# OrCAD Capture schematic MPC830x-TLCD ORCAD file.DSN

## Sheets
1 1.0_TOP_COVER: title: COVER PAGE; rev: B; company: MICETEK; note: MPC830X-TLCD
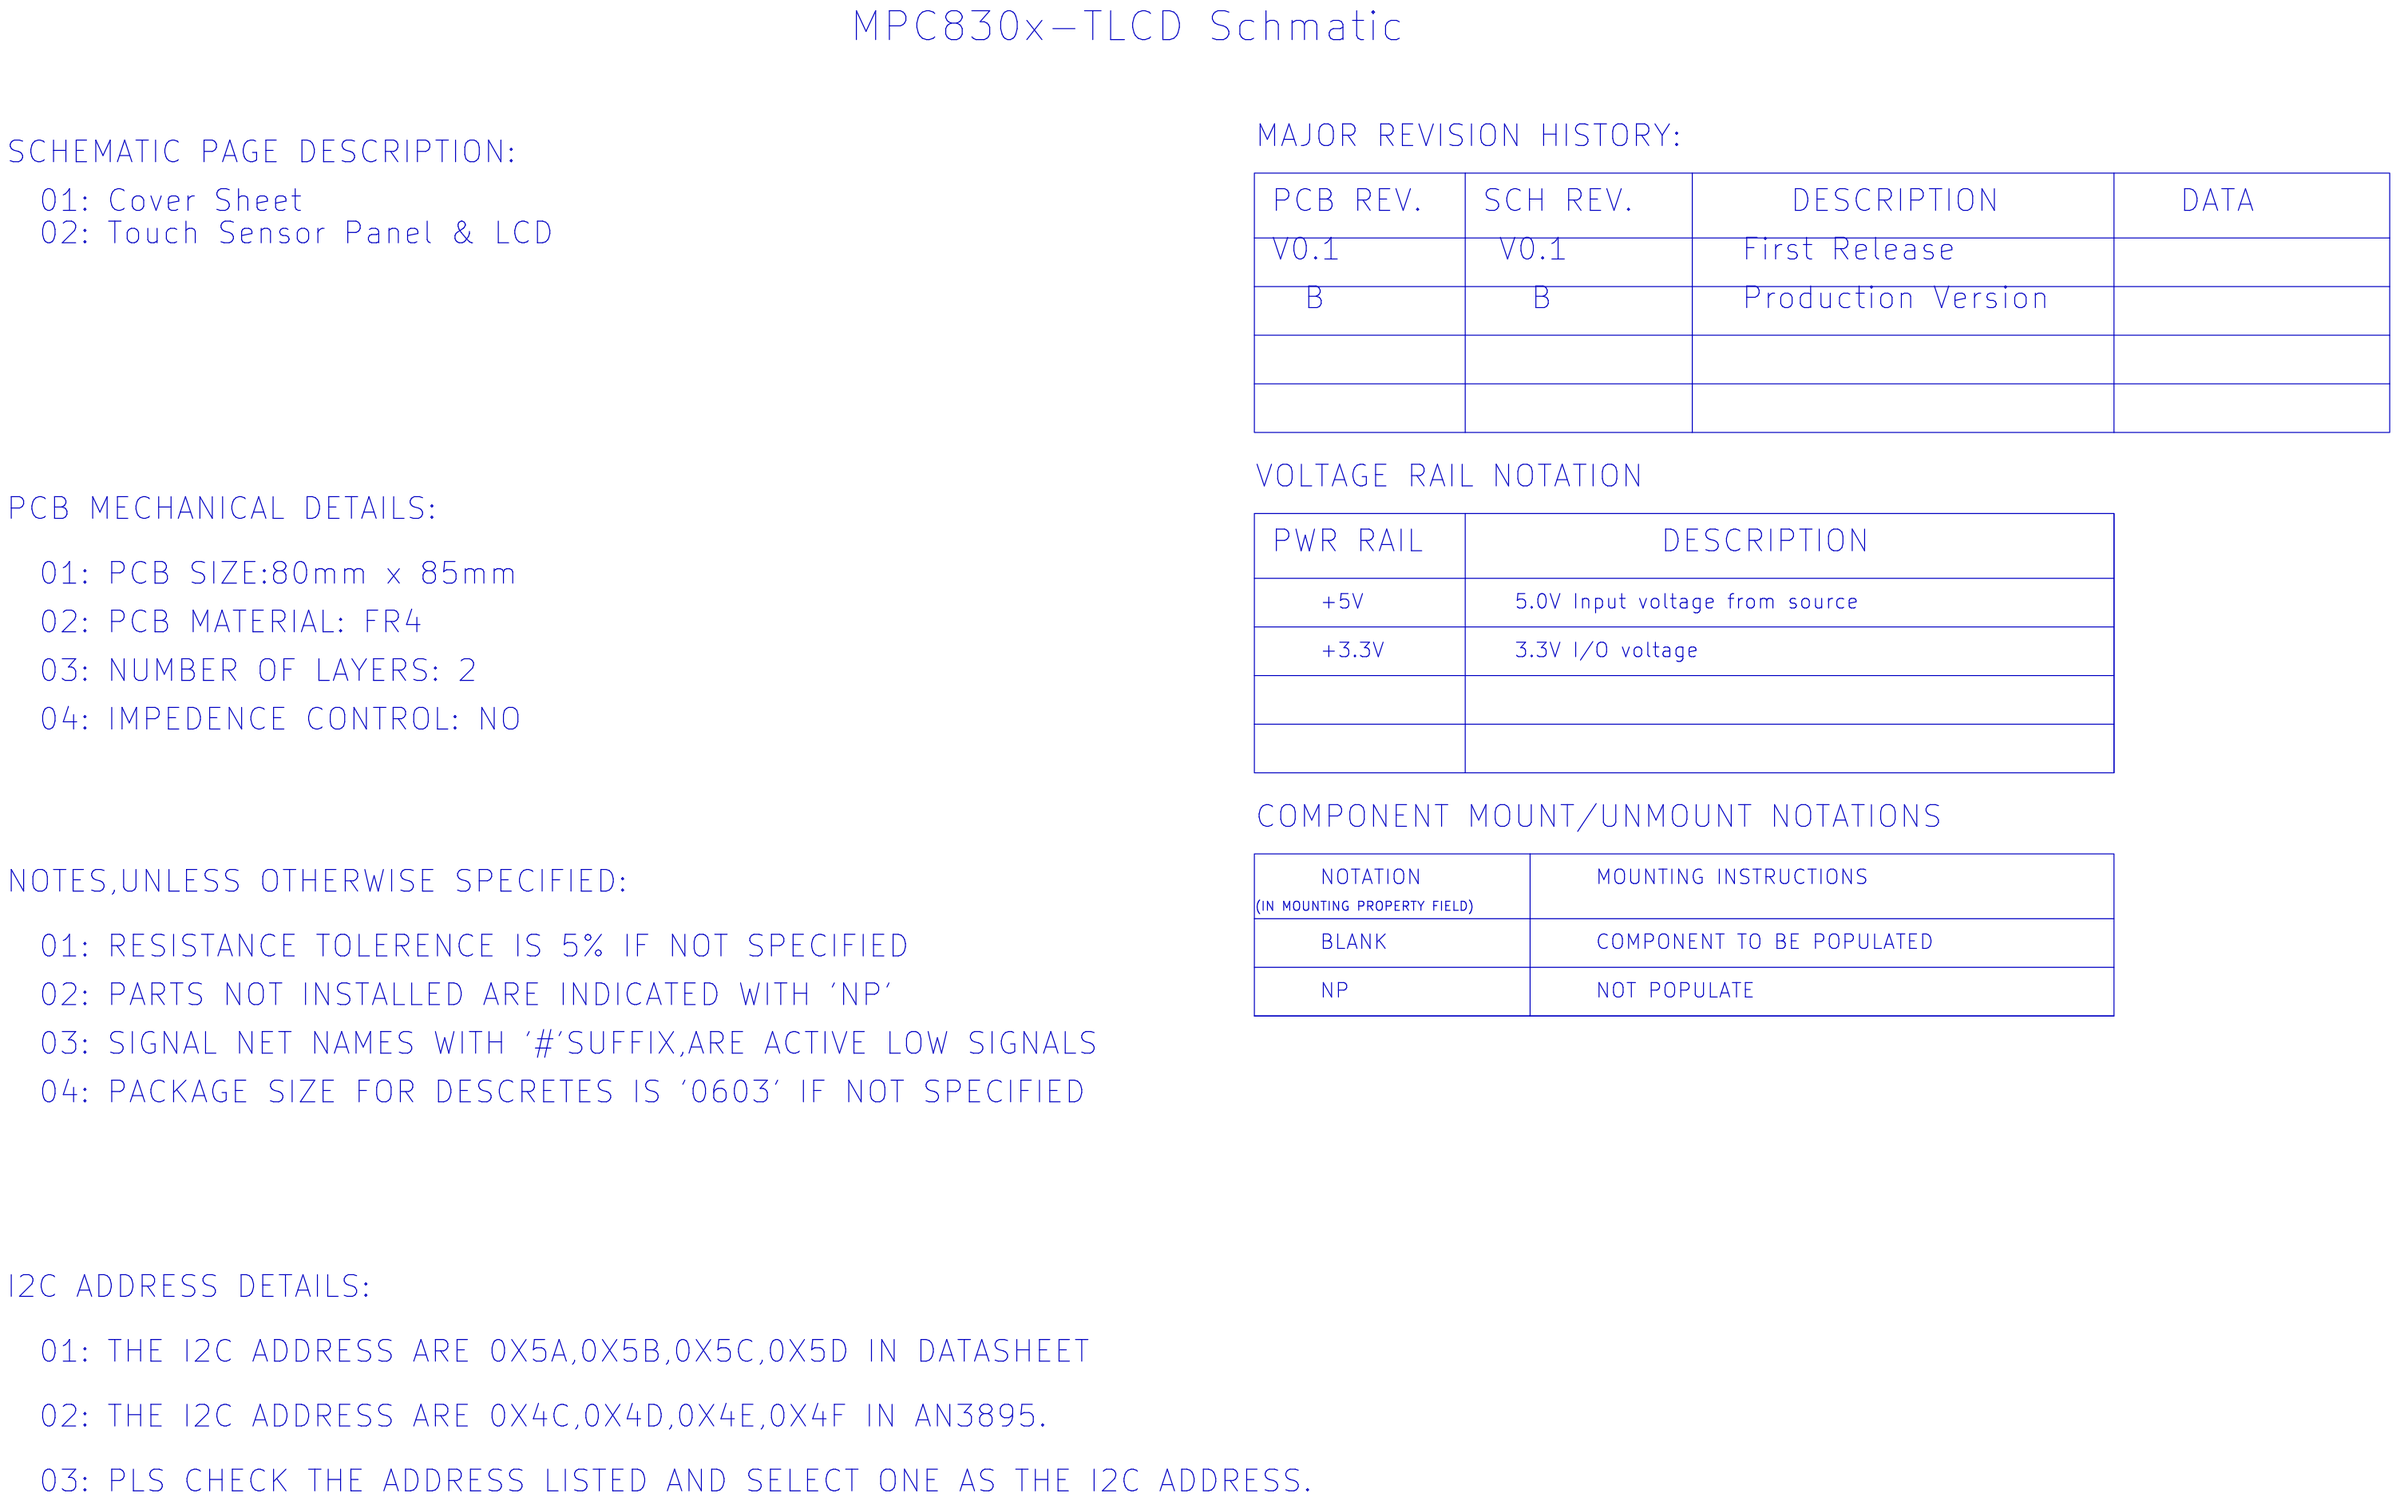
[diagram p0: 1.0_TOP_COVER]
2 1.1_MODE_CONFIG: title: MODE_CONFIG
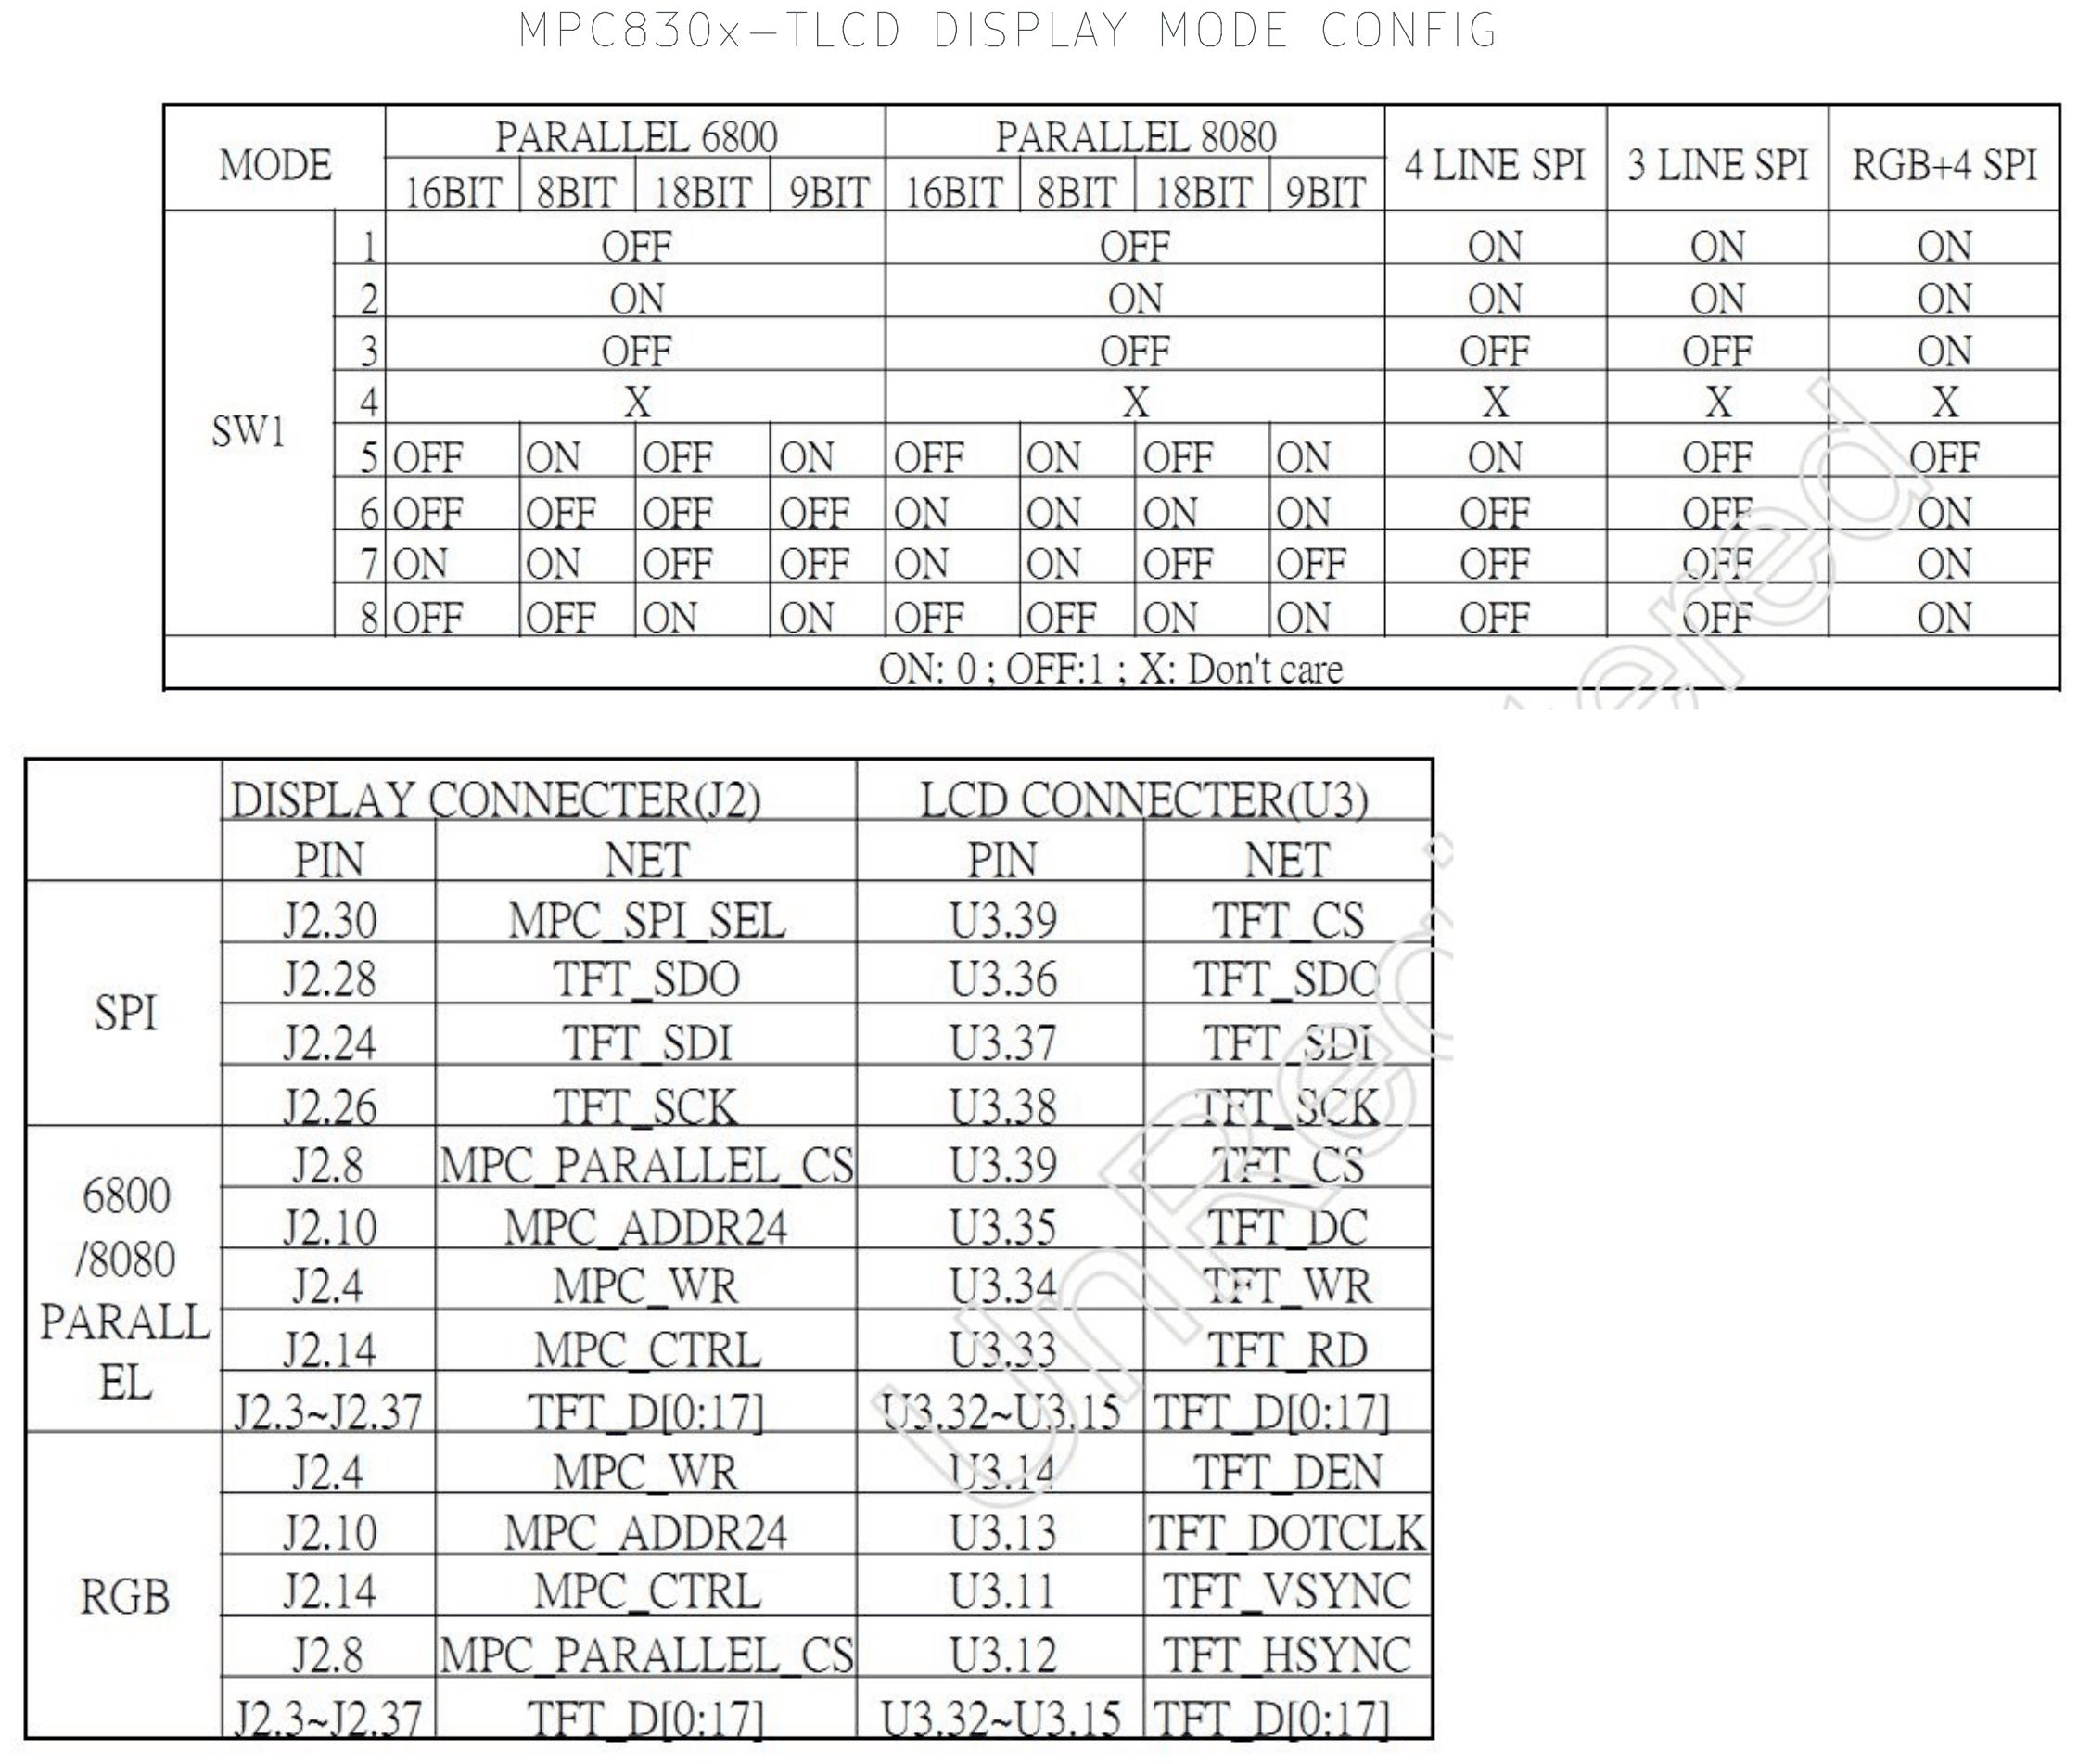
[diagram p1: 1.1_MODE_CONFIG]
3 2.0_MPC830X-TLCD_vB: size B; title: MPC830X-TLCD
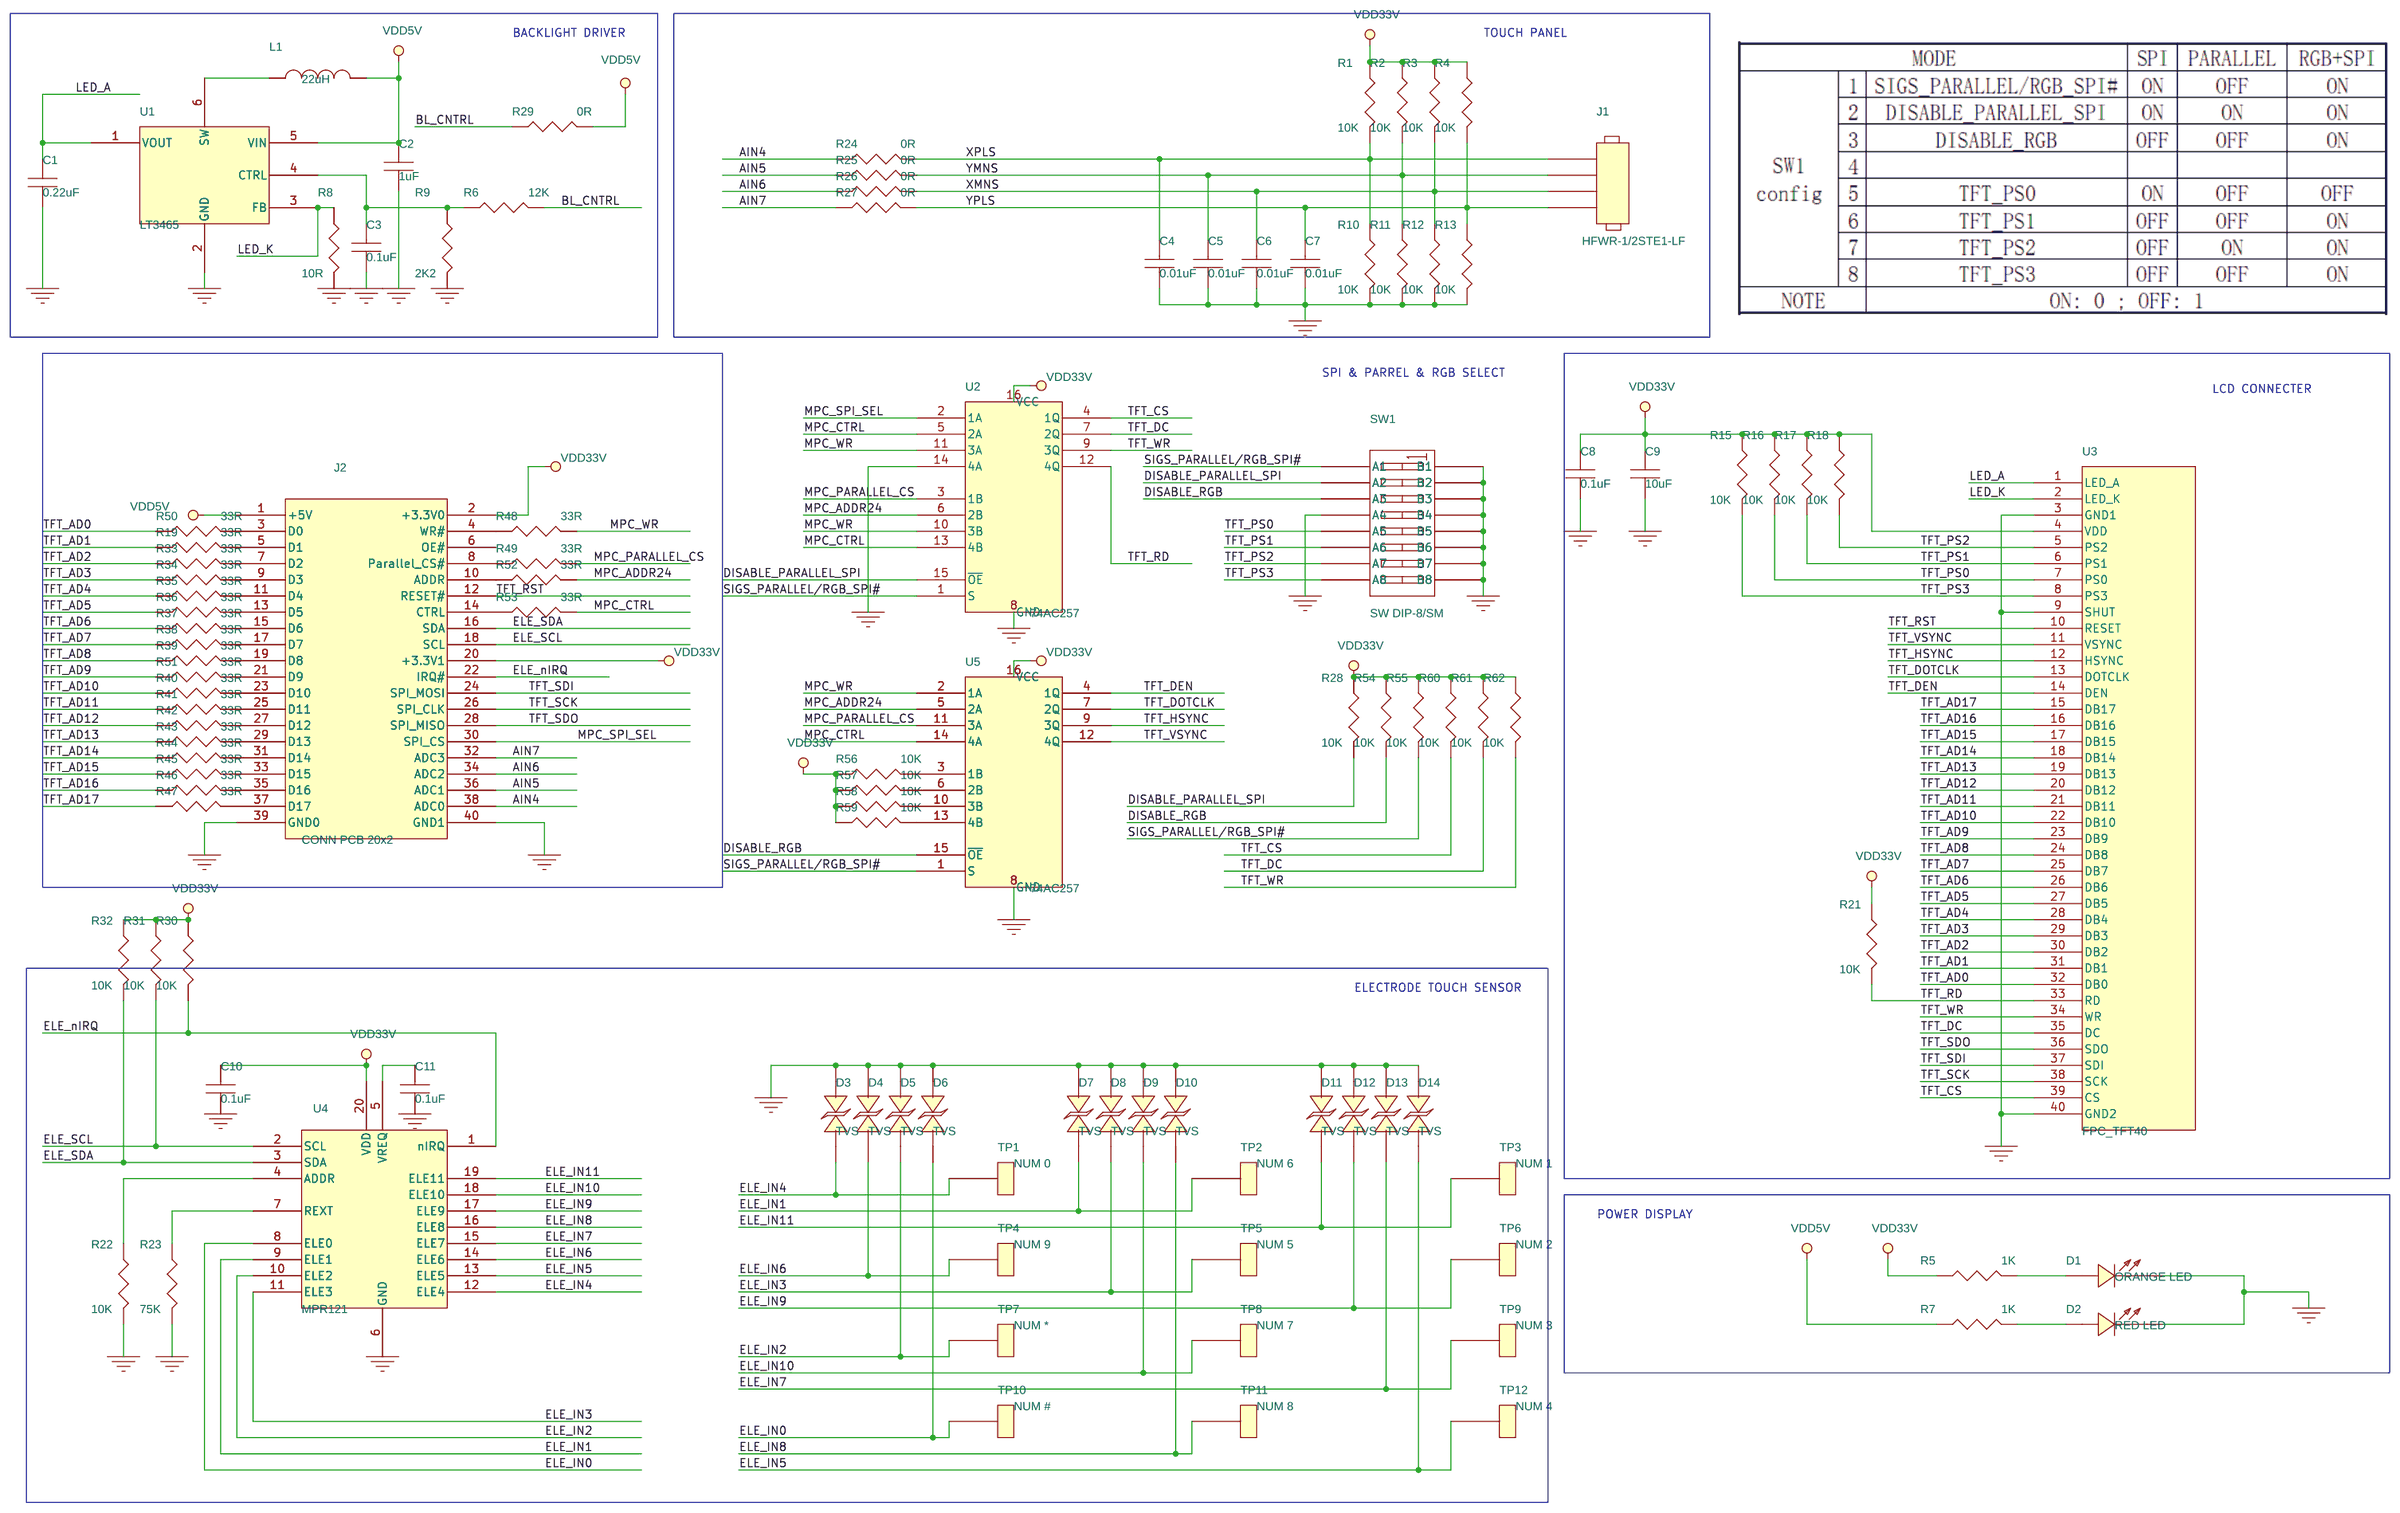
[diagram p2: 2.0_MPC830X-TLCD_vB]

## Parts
C1  0.22uF  [0603]
C2  1uF  [0603]
C3  0.1uF  [0603]
C4  0.01uF  [0603]
C5  0.01uF  [0603]
C6  0.01uF  [0603]
C7  0.01uF  [0603]
C8  0.1uF  [0603]
C9  10uF  [0805]
C10  0.1uF  [0603]
C11  0.1uF  [0603]
D1  ORANGE LED  [0603]
D2  RED LED  [0603]
D3  TVS  [0402]
D4  TVS  [0402]
D5  TVS  [0402]
D6  TVS  [0402]
D7  TVS  [0402]
D8  TVS  [0402]
D9  TVS  [0402]
D10  TVS  [0402]
D11  TVS  [0402]
D12  TVS  [0402]
D13  TVS  [0402]
D14  TVS  [0402]
J1  HFWR-1/2STE1-LF  [CON_FPC_4F_39_SM_RA_MIRRORED]
J2  CONN PCB 20x2  [HEADER_2X20_05SP_SMT_M_EDIT]
L1  22uH  [1210]
R1  10K  [0603]
R2  10K  [0603]
R3  10K  [0603]
R4  10K  [0603]
R5  1K  [0603]
R6  12K  [0603]
R7  1K  [0603]
R8  10R  [0603]
R9  2K2  [0603]
R10  10K  [0603]
R11  10K  [0603]
R12  10K  [0603]
R13  10K  [0603]
R15  10K  [0603]
R16  10K  [0603]
R17  10K  [0603]
R18  10K  [0603]
R19  33R  [0603]
R21  10K  [0603]
R22  10K  [0603]
R23  75K  [0603]
R24  0R  [0603]
R25  0R  [0603]
R26  0R  [0603]
R27  0R  [0603]
R28  10K  [0603]
R29  0R  [0603]
R30  10K  [0603]
R31  10K  [0603]
R32  10K  [0603]
R33  33R  [0603]
R34  33R  [0603]
R35  33R  [0603]
R36  33R  [0603]
R37  33R  [0603]
R38  33R  [0603]
R39  33R  [0603]
R40  33R  [0603]
R41  33R  [0603]
R42  33R  [0603]
R43  33R  [0603]
R44  33R  [0603]
R45  33R  [0603]
R46  33R  [0603]
R47  33R  [0603]
R48  33R  [0603]
R49  33R  [0603]
R50  33R  [0603]
R51  33R  [0603]
R52  33R  [0603]
R53  33R  [0603]
R54  10K  [0603]
R55  10K  [0603]
R56  10K  [0603]
R57  10K  [0603]
R58  10K  [0603]
R59  10K  [0603]
R60  10K  [0603]
R61  10K  [0603]
R62  10K  [0603]
SW1  SW DIP-8/SM  [97C08]
TP1  NUM 0  [electrode_sq_10mm]
TP2  NUM 6  [electrode_sq_10mm]
TP3  NUM 1  [electrode_sq_10mm]
TP4  NUM 9  [electrode_sq_10mm]
TP5  NUM 5  [electrode_sq_10mm]
TP6  NUM 2  [electrode_sq_10mm]
TP7  NUM *  [electrode_sq_10mm]
TP8  NUM 7  [electrode_sq_10mm]
TP9  NUM 3  [electrode_sq_10mm]
TP10  NUM #  [electrode_sq_10mm]
TP11  NUM 8  [electrode_sq_10mm]
TP12  NUM 4  [electrode_sq_10mm]
U1  LT3465  [SOT23_6]
U2  74AC257  [SO16]
U3  FPC_TFT40  [CON_FPC_40F_0P5_SM_RA_MIRRORED]
U4  MPR121  [QFN20_0P4_3X3MM]
U5  74AC257  [SO16]

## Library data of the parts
C1-C11 = CAP_NP
D1 D2 = LED
D3-D14 = DIODE_TVS_BI-DIR
J1 = 4_HEADER
J2 = CONN_PCB_20x2_1
L1 = CHOKE
R1-R13 R15-R19 R21-R62 = R
SW1 = SW_DIP-8_SM_0
TP1-TP12 = TEST_POINT
U1 = LT3465
U2 U5 = 74AC257
U3 = FPC_TFT40_0
U4 = MPR121

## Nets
GND: C1.2 C2.2 C3.2 C4.2 C5.2 C6.2 C7.2 C8.2 C9.2 C10.2 C11.2 D1.2(CATHODE) D2.2(CATHODE) D3.2 D4.2 D5.2 D6.2 D7.2 D8.2 D9.2 D10.2 D11.2 D12.2 D13.2 D14.2 J2.39(GND0) J2.40(GND1) R8.2 R9.2 R10.2 R11.2 R12.2 R13.2 R22.2 R23.2 SW1.4(A4) SW1.9(B8) SW1.10(B7) SW1.11(B6) SW1.12(B5) SW1.13(B4) SW1.14(B3) SW1.15(B2) SW1.16(B1) U1.2(GND) U2.8(GND) U2.14(4A) U3.3(GND1) U3.9(SHUT) U3.40(GND2) U4.6(GND) U5.8(GND)
VDD5V: C2.1 J2.1(+5V) L1.2 R7.1 R29.2 U1.5(VIN)
VDD33V: C8.1 C9.1 C10.1 J2.2(+3.3V0) J2.20(+3.3V1) R1.1 R2.1 R3.1 R4.1 R5.1 R15.1 R16.1 R17.1 R18.1 R21.1 R28.1 R30.1 R31.1 R32.1 R54.1 R55.1 R56.1 R57.1 R58.1 R59.1 R60.1 R61.1 R62.1 U2.16(VCC) U3.4(VDD) U4.20(VDD) U5.16(VCC)
AIN4: J2.38(ADC0) R24.1
AIN5: J2.36(ADC1) R25.1
AIN6: J2.34(ADC2) R26.1
AIN7: J2.32(ADC3) R27.1
BL_CNTRL: R6.2 R29.1
DISABLE_PARALLEL_SPI: R28.2 SW1.2(A2) U2.15(~{OE})
DISABLE_RGB: R54.2 SW1.3(A3) U5.15(~{OE})
ELE_IN0: D6.1 TP10.1 U4.8(ELE0)
ELE_IN1: D7.1 TP2.1 U4.9(ELE1)
ELE_IN2: D5.1 TP7.1 U4.10(ELE2)
ELE_IN3: D8.1 TP5.1 U4.11(ELE3)
ELE_IN4: D3.1 TP1.1 U4.12(ELE4)
ELE_IN5: D14.1 TP12.1 U4.13(ELE5)
ELE_IN6: D4.1 TP4.1 U4.14(ELE6)
ELE_IN7: D13.1 TP9.1 U4.15(ELE7)
ELE_IN8: D10.1 TP11.1 U4.16(ELE8)
ELE_IN9: D12.1 TP6.1 U4.17(ELE9)
ELE_IN10: D9.1 TP8.1 U4.18(ELE10)
ELE_IN11: D11.1 TP3.1 U4.19(ELE11)
ELE_nIRQ: J2.22(IRQ#) R30.2 U4.1(nIRQ)
ELE_SCL: J2.18(SCL) R31.2 U4.2(SCL)
ELE_SDA: J2.16(SDA) R32.2 U4.3(SDA)
LED_A: C1.1 U1.1(VOUT) U3.1(LED_A)
LED_K: R8.1 U1.3(FB) U3.2(LED_K)
MPC_ADDR24: R52.2 U2.6(2B) U5.5(2A)
MPC_CTRL: R53.2 U2.5(2A) U2.13(4B) U5.14(4A)
MPC_PARALLEL_CS: R49.2 U2.3(1B) U5.11(3A)
MPC_SPI_SEL: J2.30(SPI_CS) U2.2(1A)
MPC_WR: R48.2 U2.10(3B) U2.11(3A) U5.2(1A)
SIGS_PARALLEL/RGB_SPI#: R55.2 SW1.1(A1) U2.1(S) U5.1(S)
TFT_AD0: R50.1 U3.32(DB0)
TFT_AD1: R19.1 U3.31(DB1)
TFT_AD2: R33.1 U3.30(DB2)
TFT_AD3: R34.1 U3.29(DB3)
TFT_AD4: R35.1 U3.28(DB4)
TFT_AD5: R36.1 U3.27(DB5)
TFT_AD6: R37.1 U3.26(DB6)
TFT_AD7: R38.1 U3.25(DB7)
TFT_AD8: R39.1 U3.24(DB8)
TFT_AD9: R51.1 U3.23(DB9)
TFT_AD10: R40.1 U3.22(DB10)
TFT_AD11: R41.1 U3.21(DB11)
TFT_AD12: R42.1 U3.20(DB12)
TFT_AD13: R43.1 U3.19(DB13)
TFT_AD14: R44.1 U3.18(DB14)
TFT_AD15: R45.1 U3.17(DB15)
TFT_AD16: R46.1 U3.16(DB16)
TFT_AD17: R47.1 U3.15(DB17)
TFT_CS: R60.2 U2.4(1Q) U3.39(CS)
TFT_DC: R61.2 U2.7(2Q) U3.35(DC)
TFT_DEN: U3.14(DEN) U5.4(1Q)
TFT_DOTCLK: U3.13(DOTCLK) U5.7(2Q)
TFT_HSYNC: U3.12(HSYNC) U5.9(3Q)
TFT_PS0: R16.2 SW1.5(A5) U3.7(PS0)
TFT_PS1: R17.2 SW1.6(A6) U3.6(PS1)
TFT_PS2: R18.2 SW1.7(A7) U3.5(PS2)
TFT_PS3: R15.2 SW1.8(A8) U3.8(PS3)
TFT_RD: R21.2 U2.12(4Q) U3.33(RD)
TFT_RST: J2.12(RESET#) U3.10(RESET)
TFT_SCK: J2.26(SPI_CLK) U3.38(SCK)
TFT_SDI: J2.24(SPI_MOSI) U3.37(SDI)
TFT_SDO: J2.28(SPI_MISO) U3.36(SDO)
TFT_VSYNC: U3.11(VSYNC) U5.12(4Q)
TFT_WR: R62.2 U2.9(3Q) U3.34(WR)
XMNS: C6.1 J1.3 R3.2 R12.1 R26.2
XPLS: C4.1 J1.1 R1.2 R10.1 R24.2
YMNS: C5.1 J1.2 R2.2 R11.1 R25.2
YPLS: C7.1 J1.4 R4.2 R13.1 R27.2
N22324856: L1.1 U1.6(SW)
N22335128: C3.1 R6.1 R9.1 U1.4(CTRL)
N22381223: R23.1 U4.7(REXT)
N22384710: C11.1 U4.5(VREQ)
N22385598: R22.1 U4.4(ADDR)
N22863366: D1.1(ANODE) R5.2
N22863376: D2.1(ANODE) R7.2
N22873501: J2.9(D3) R34.2
N22873502: J2.13(D5) R36.2
N22873504: J2.15(D6) R37.2
N22873505: J2.17(D7) R38.2
N22873506: J2.19(D8) R39.2
N22873507: J2.33(D15) R45.2
N22873508: J2.21(D9) R51.2
N22873509: J2.23(D10) R40.2
N22873510: J2.25(D11) R41.2
N22873511: J2.27(D12) R42.2
N22873512: R59.2 U5.13(4B)
N22873513: R58.2 U5.10(3B)
N22873514: J2.29(D13) R43.2
N22873515: R57.2 U5.6(2B)
N22873516: J2.31(D14) R44.2
N22873517: J2.14(CTRL) R53.1
N22873518: R56.2 U5.3(1B)
N22873519: J2.35(D16) R46.2
N22873520: J2.37(D17) R47.2
N22873521: J2.5(D1) R19.2
N22873522: J2.10(ADDR) R52.1
N22873523: J2.3(D0) R50.2
N22873524: J2.4(WR#) R48.1
N22873526: J2.7(D2) R33.2
N22873527: J2.8(Parallel_CS#) R49.1
N22873528: J2.11(D4) R35.2

Not connected (* = marked no-connect by the designer): J2 6(OE#)

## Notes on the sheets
sheet 1
- MPC830x-TLCD Schmatic
- MAJOR REVISION HISTORY:
- SCHEMATIC PAGE DESCRIPTION:
- 01: Cover Sheet
- PCB REV.
- SCH REV.
- DESCRIPTION
- DATA
- 02: Touch Sensor Panel & LCD
- V0.1
- V0.1
- First Release
- B
- B
- Production Version
- VOLTAGE RAIL NOTATION
- PCB MECHANICAL DETAILS:
- PWR RAIL
- DESCRIPTION
- 01: PCB SIZE:80mm x 85mm
- 02: PCB MATERIAL: FR4
- +5V
- 5.0V Input voltage from source
- +3.3V
- 3.3V I/O voltage
- 03: NUMBER OF LAYERS: 2
- 04: IMPEDENCE CONTROL: NO
- COMPONENT MOUNT/UNMOUNT NOTATIONS
- NOTES,UNLESS OTHERWISE SPECIFIED:
- NOTATION
- MOUNTING INSTRUCTIONS
- (IN MOUNTING PROPERTY FIELD)
- 01: RESISTANCE TOLERENCE IS 5% IF NOT SPECIFIED
- BLANK
- COMPONENT TO BE POPULATED
- 02: PARTS NOT INSTALLED ARE INDICATED WITH 'NP'
- NP
- NOT POPULATE
- 03: SIGNAL NET NAMES WITH '#'SUFFIX,ARE ACTIVE LOW SIGNALS
- 04: PACKAGE SIZE FOR DESCRETES IS '0603' IF NOT SPECIFIED
- I2C ADDRESS DETAILS:
- 01: THE I2C ADDRESS ARE 0X5A,0X5B,0X5C,0X5D IN DATASHEET
- 02: THE I2C ADDRESS ARE 0X4C,0X4D,0X4E,0X4F IN AN3895.
- 03: PLS CHECK THE ADDRESS LISTED AND SELECT ONE AS THE I2C ADDRESS.
sheet 2
- MPC830x-TLCD DISPLAY MODE CONFIG
sheet 3
- BACKLIGHT DRIVER
- TOUCH PANEL
- SPI & PARREL & RGB SELECT
- LCD CONNECTER
- ELECTRODE TOUCH SENSOR
- POWER DISPLAY
